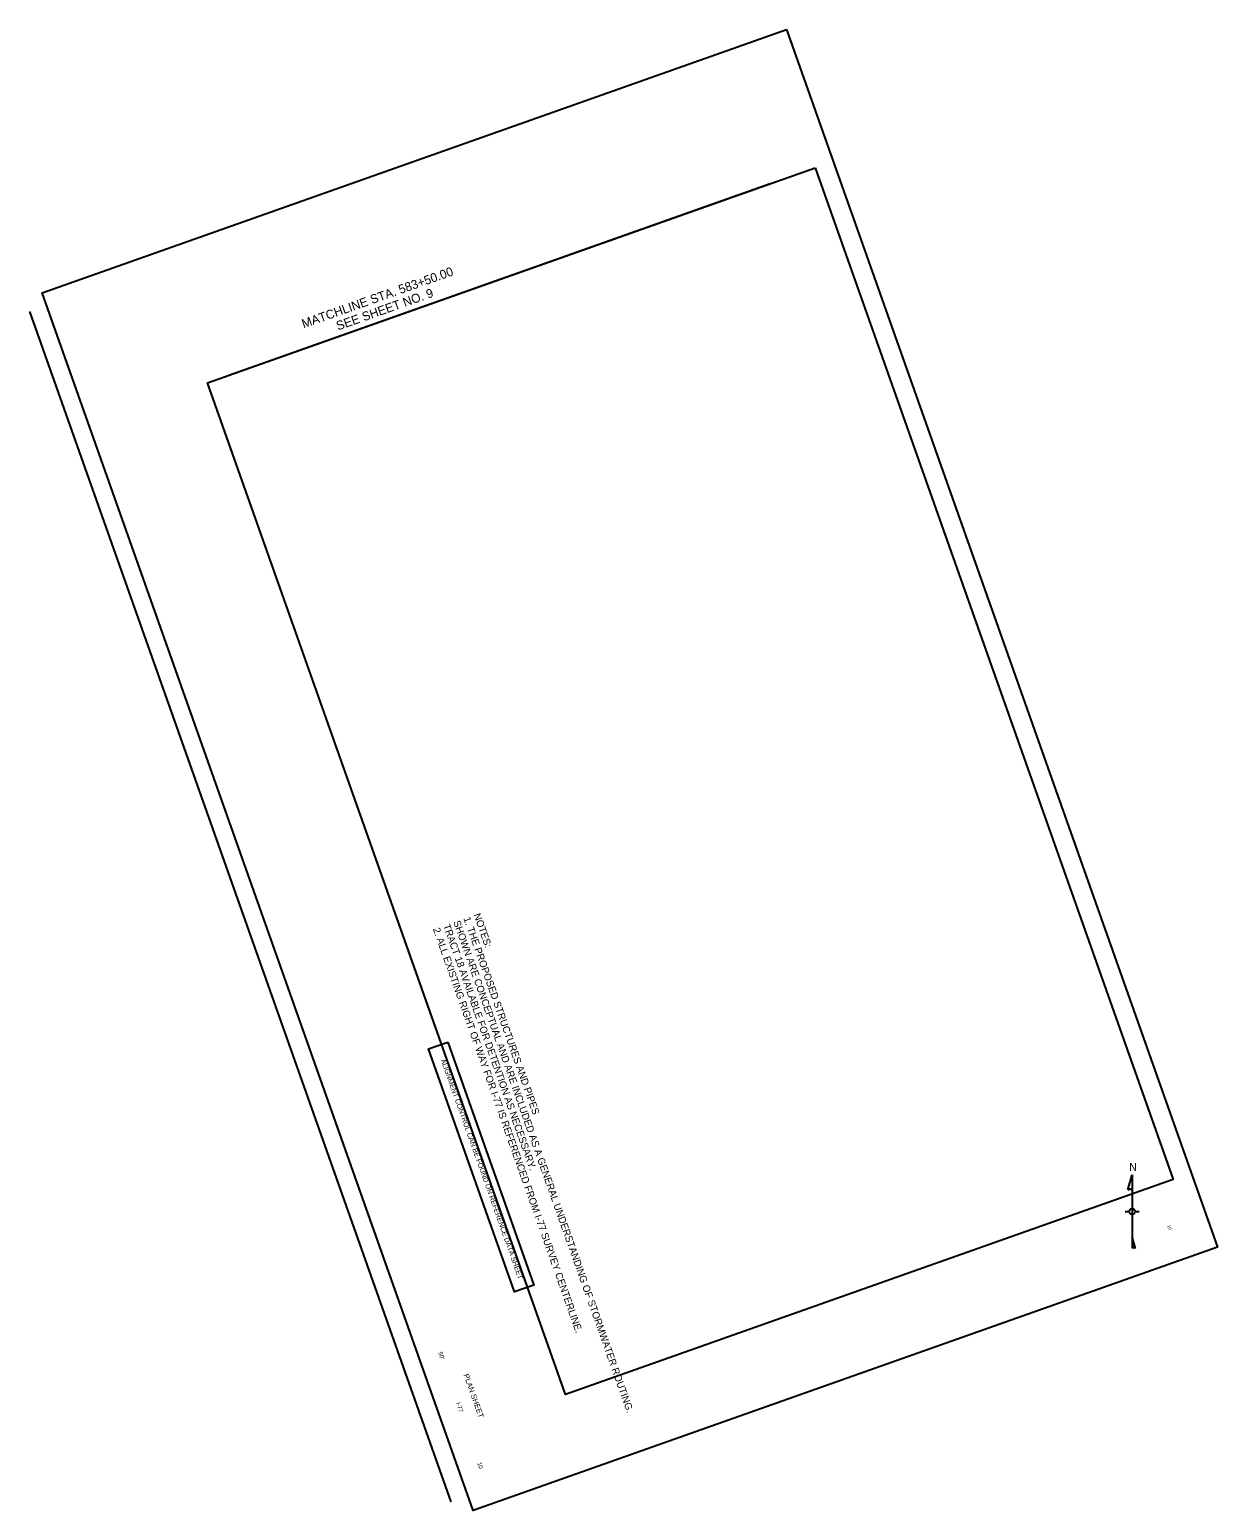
# Model space of a CAD drawing. Extents: x 2006190 to 2007845, y 1133293 to 1135356.
import ezdxf

# ---------------------------------------------------------------- set-up
doc = ezdxf.new("R2010")
doc.units = 0
for name, color, linetype in [('North Arrow', 7, 'Continuous'), ('RD_SHT_IplotShp', 7, 'Continuous'), ('RD_SHT_MatchLine', 7, 'Continuous'), ('RD_SHT_Misc1', 7, 'Continuous'), ('RD_SHT_ShtClip', 7, 'Continuous'), ('RD_SHT_TX', 7, 'Continuous')]:
    doc.layers.add(name, color=color, linetype=linetype)

msp = doc.modelspace()

# ---------------------------------------------------------------- linework, layer by layer
at = {"layer": 'North Arrow'}
for p, q in [((2007719.9, 1133739.2), (2007725.8, 1133760.2)), ((2007725.8, 1133760.2), (2007725.8, 1133738)), ((2007725.8, 1133760.2), (2007725.8, 1133658)), ((2007716.1, 1133709.1), (2007721.8, 1133709.1)), ((2007729.8, 1133709.1), (2007735.5, 1133709.1)), ((2007725.8, 1133673.8), (2007725.8, 1133658)), ((2007730.3, 1133657.7), (2007725.8, 1133673.8))]:
    msp.add_line(p, q, dxfattribs=at)
msp.add_circle((2007725.8, 1133709.1), 4.02, dxfattribs=at)
for centre, radius, start, end in [((2007722.5, 1133736.7), 3.59, 22.3707, 136.1387), ((2007727.9, 1133655.5), 3.3, 43.3397, 130.5607)]:
    msp.add_arc(centre, radius, start, end, dxfattribs=at)
at = {"layer": 'RD_SHT_IplotShp'}
msp.add_lwpolyline([(2007244.2, 1135356.5), (2007844.5, 1133659.5), (2006807.5, 1133292.7), (2006207.2, 1134989.6)], close=True, dxfattribs=at)
at = {"layer": 'RD_SHT_MatchLine'}
msp.add_line((2007221.5, 1135141.4), (2006467.3, 1134874.6), dxfattribs=at)
at = {"layer": 'RD_SHT_ShtClip'}
msp.add_lwpolyline([(2007284.4, 1135163.6), (2007783.1, 1133753.9), (2006936.5, 1133454.4), (2006437.8, 1134864.1)], close=True, dxfattribs=at)
at = {"layer": 'RD_SHT_TX'}
msp.add_line((2006189.8, 1134963.7), (2006776.8, 1133304.5), dxfattribs=at)
msp.add_lwpolyline([(2006772.5, 1133945.2), (2006892.3, 1133606.6), (2006865.5, 1133597.2), (2006745.7, 1133935.8)], close=True, dxfattribs=at)

# ---------------------------------------------------------------- texts
at = {"layer": 'North Arrow'}
msp.add_text('N', height=11.1, dxfattribs=at).set_placement((2007721.7, 1133765.7))
at = {"layer": 'RD_SHT_MatchLine'}
for s, p in [('MATCHLINE STA. 583+50.00', (2006571.5, 1134940.1)), ('SEE SHEET NO. 9', (2006619.5, 1134937.1))]:
    msp.add_text(s, height=12.5, rotation=19.482, dxfattribs=at).set_placement(p)
at = {"layer": 'RD_SHT_Misc1'}
for s, p in [('NOTES:', (2006808.1, 1134122.8)), ('2. ALL EXISTING RIGHT OF WAY FOR I-77 IS REFERENCED FROM I-77 SURVEY CENTERLINE.', (2006751.5, 1134102.8)), ('TRACT 18 AVAILABLE FOR DETENTION AS NECESSARY. ', (2006765.7, 1134107.8)), ('SHOWN ARE CONCEPTUAL AND ARE INCLUDED AS A GENERAL UNDERSTANDING OF STORMWATER ROUTING.  ', (2006779.8, 1134112.8)), ('1. THE PROPOSED STRUCTURES AND PIPES ', (2006794, 1134117.8))]:
    msp.add_text(s, height=10, rotation=289.482, dxfattribs=at).set_placement(p)
at = {"layer": 'RD_SHT_TX'}
for s, height, p in [('ALIGNMENT CONTROL CAN BE FOUND ON REFERENCE DATA SHEET', 7, (2006762.4, 1133920.6)), ('10', 4.5, (2007774.5, 1133689.6)), ("50'", 6, (2006758.9, 1133512.5)), ('PLAN SHEET', 7.5, (2006794.2, 1133481.5)), ('I-77', 6, (2006783.8, 1133442)), ('10', 6, (2006813.3, 1133358.6))]:
    msp.add_text(s, height=height, rotation=289.482, dxfattribs=at).set_placement(p)

doc.saveas('drawing.dxf')
